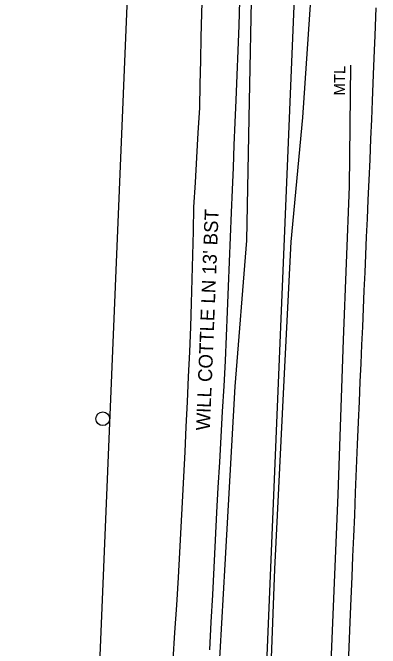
# Model space of a CAD drawing. Extents: x 2262665 to 2270527, y 505476 to 514960.
# Drawn here: x 2266169.2 to 2266301.4, y 511256.2 to 511484.8 of the extents above; entities that cross this region are included whole.
import ezdxf

# ---------------------------------------------------------------- set-up
doc = ezdxf.new("R2010")
doc.units = 0
for name, color, linetype in [('Exist Guardrail', 7, 'Continuous'), ('Exist Guardrail Text', 7, 'Continuous'), ('Exist Hydro Stream or Body of Water', 7, 'Continuous'), ('Exist Right of Way Control of Access CA Symbol CELL', 7, 'Continuous'), ('Exist Right of Way Control of Access Line', 7, 'Continuous'), ('Exist Right of Way Line', 7, 'Continuous'), ('Exist Roads EOP', 7, 'Continuous'), ('Exist Roads EOP Text', 7, 'Continuous'), ('Exist Utilities Other Pole CELL', 7, 'Continuous')]:
    doc.layers.add(name, color=color, linetype=linetype)

msp = doc.modelspace()

# ---------------------------------------------------------------- linework, layer by layer
at = {"layer": 'Exist Guardrail'}
msp.add_lwpolyline([(2266281.35, 511189.41), (2266283.51, 511245.19), (2266286.28, 511311.47), (2266288.16, 511367.12), (2266290.33, 511422.26), (2266290.78, 511465.99)], dxfattribs=at)
at = {"layer": 'Exist Hydro Stream or Body of Water'}
for points in [[(2266274.13, 511656.9), (2266285.13, 511659.83), (2266298.69, 511655.35), (2266301.39, 511640.07), (2266298.87, 511606.11), (2266296.18, 511561.33), (2266276.32, 511489.55), (2266273.39, 511447.18), (2266269.15, 511402.44), (2266266.62, 511350.29), (2266263.29, 511284.61), (2266261.41, 511233.5)], [(2266242.57, 511233.58), (2266245.62, 511286.27), (2266249.21, 511350.34), (2266253.36, 511402.9), (2266254.17, 511446.9), (2266255.33, 511501.23), (2266258.4, 511561.12), (2266266.85, 511608.7), (2266269.9, 511649.03)]]:
    msp.add_lwpolyline(points, dxfattribs=at)
at = {"layer": 'Exist Right of Way Control of Access CA Symbol CELL'}
msp.add_line((2266260.83, 511256.36), (2266260.83, 511256.36), dxfattribs=at)
at = {"layer": 'Exist Right of Way Control of Access Line'}
msp.add_line((2266232.79, 510577.78), (2266283.35, 511801.46), dxfattribs=at)
at = {"layer": 'Exist Right of Way Line'}
msp.add_line((2266169.17, 510491.24), (2266223.4, 511803.97), dxfattribs=at)
at = {"layer": 'Exist Roads EOP'}
for points in [[(2266237.33, 511492.45), (2266237.08, 511484.6), (2266236.89, 511476.09), (2266236.69, 511467.58), (2266236.5, 511459.07), (2266236.3, 511450.56), (2266235.79, 511441.63), (2266235.27, 511432.7), (2266234.76, 511423.77), (2266234.24, 511414.84), (2266234.02, 511406.22), (2266233.8, 511397.61), (2266233.58, 511388.99), (2266233.35, 511380.38), (2266233.13, 511371.77), (2266232.72, 511362.79), (2266232.31, 511353.81), (2266231.89, 511344.83), (2266231.48, 511335.86), (2266231.07, 511326.88), (2266230.59, 511317.82), (2266230.11, 511308.77), (2266229.63, 511299.72), (2266229.15, 511290.66), (2266228.67, 511281.61), (2266228.03, 511271.74), (2266227.39, 511261.87), (2266226.75, 511252)], [(2266240.12, 511255.67), (2266240.61, 511265.53), (2266241.11, 511275.39), (2266241.6, 511285.25), (2266242.1, 511295.11), (2266242.6, 511304.97), (2266243.12, 511314.07), (2266243.64, 511323.18), (2266244.16, 511332.28), (2266244.68, 511341.39), (2266245.21, 511350.49), (2266245.73, 511359.6), (2266246.08, 511368.49), (2266246.42, 511377.39), (2266246.77, 511386.28), (2266247.12, 511395.18), (2266247.46, 511404.08), (2266247.81, 511412.97), (2266248.17, 511421.06), (2266248.53, 511429.14), (2266248.88, 511437.23), (2266249.24, 511445.31), (2266249.6, 511453.4), (2266249.93, 511462.33), (2266250.25, 511471.26), (2266250.58, 511480.2), (2266250.91, 511489.13)], [(2266299.83, 511486.58), (2266299.43, 511476.6), (2266299.22, 511471.24), (2266298.99, 511465.55), (2266298.75, 511459.52), (2266298.5, 511453.16), (2266298.22, 511446.46), (2266297.92, 511439.41), (2266297.59, 511432.03), (2266297.26, 511424.62), (2266296.94, 511417.5), (2266296.64, 511410.68), (2266296.35, 511404.16), (2266296.07, 511397.77), (2266295.79, 511391.35), (2266295.51, 511384.89), (2266295.22, 511378.4), (2266294.94, 511371.87), (2266294.65, 511365.29), (2266294.37, 511358.66), (2266294.08, 511351.98), (2266293.78, 511345), (2266293.46, 511337.49), (2266293.13, 511329.44), (2266292.77, 511320.85), (2266292.41, 511312.23), (2266292.07, 511304.08), (2266291.75, 511296.41), (2266291.45, 511289.21), (2266291.14, 511281.94), (2266290.81, 511274.08), (2266290.45, 511265.62), (2266290.06, 511256.57), (2266289.67, 511247.39)]]:
    msp.add_lwpolyline(points, dxfattribs=at)
at = {"layer": 'Exist Utilities Other Pole CELL'}
msp.add_circle((2266201.54, 511338.74), 2.46, dxfattribs=at)

# ---------------------------------------------------------------- texts
at = {"layer": 'Exist Guardrail Text'}
msp.add_text('MTL', height=4, rotation=89.403, dxfattribs=at).set_placement((2266288.67, 511455.03))
at = {"layer": 'Exist Roads EOP Text'}
msp.add_text("WILL COTTLE LN 13' BST", height=5, rotation=87.7086, dxfattribs=at).set_placement((2266240.09, 511334.45))

doc.saveas('drawing.dxf')
